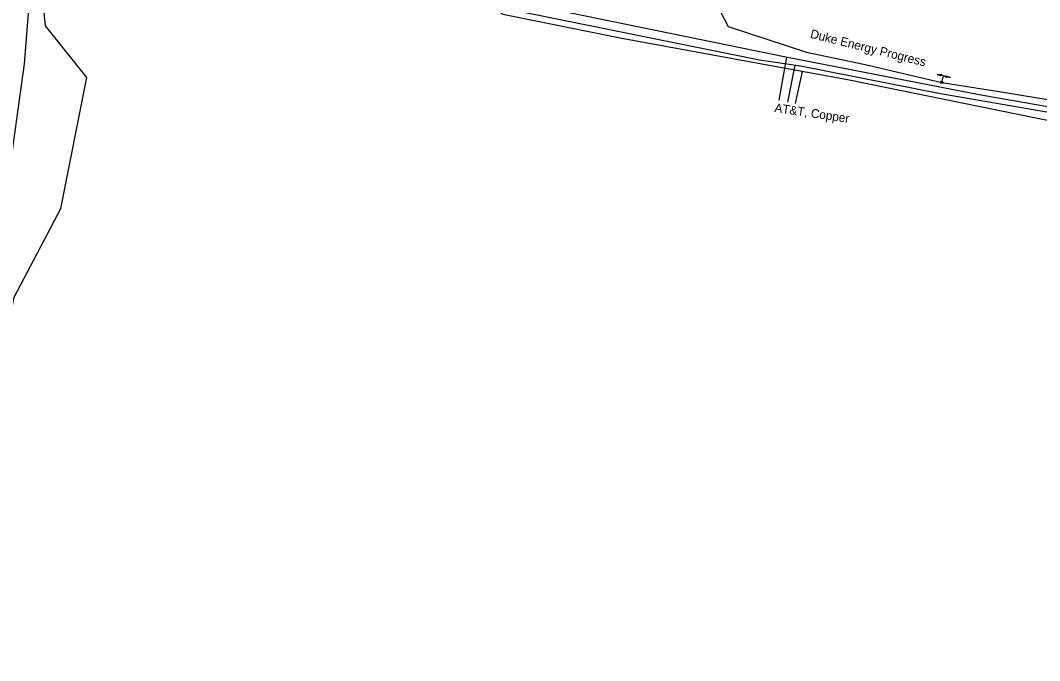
# Model space of a CAD drawing. Extents: x 2070721 to 2083340, y 729290 to 737883.
# Drawn here: x 2082363.4 to 2082825.8, y 735917.7 to 736208.1 of the extents above; entities that cross this region are included whole.
import ezdxf

# ---------------------------------------------------------------- set-up
doc = ezdxf.new("R2010")
doc.units = 0
for name, color, linetype in [('Exist Utilities Power Change of Service SUE CELL', 7, 'Continuous'), ('Exist Utilities Power UG Cable SUE LOS B', 7, 'Continuous'), ('Exist Utilities Power UG Cable SUE LOS C', 7, 'Continuous'), ('Exist Utilities Power UG Cable SUE LOS C Text', 7, 'Continuous'), ('Exist Utilities Telephone UG Cable SUE LOS C', 7, 'Continuous'), ('Exist Utilities Telephone UG Cable SUE LOS C Leader', 7, 'Continuous'), ('Exist Utilities Telephone UG Cable SUE LOS C Text', 7, 'Continuous'), ('Exist Utilities Telephone UG Conduit SUE LOS B', 7, 'Continuous')]:
    doc.layers.add(name, color=color, linetype=linetype)

msp = doc.modelspace()

# ---------------------------------------------------------------- linework, layer by layer
at = {"layer": 'Exist Utilities Power Change of Service SUE CELL'}
for p, q in [((2082785.15, 736182.29), (2082779.35, 736183.65)), ((2082781.39, 736180), (2082782.1, 736183.01)), ((2082782.1, 736183.01), (2082785.15, 736182.29)), ((2082781.39, 736180), (2082781.39, 736180))]:
    msp.add_line(p, q, dxfattribs=at)
for points in [[(2082779.35, 736183.65), (2082781.34, 736183.54), (2082780.86, 736183.3), (2082781.16, 736182.91)], [(2082785.15, 736182.29), (2082783.15, 736182.41), (2082783.64, 736182.65), (2082783.34, 736183.03)]]:
    msp.add_lwpolyline(points, close=True, dxfattribs=at)
msp.add_circle((2082781.39, 736180), 0.517, dxfattribs=at)
at = {"layer": 'Exist Utilities Power UG Cable SUE LOS B'}
msp.add_lwpolyline([(2082781.39, 736180), (2082807.5, 736175.87), (2082843.27, 736169.98), (2082869.14, 736165.45), (2082887.28, 736166.47), (2082906.47, 736166.59), (2082946.98, 736169.49)], dxfattribs=at)
at = {"layer": 'Exist Utilities Power UG Cable SUE LOS C'}
msp.add_lwpolyline([(2082666.83, 736239.42), (2082684.44, 736205.31), (2082720.04, 736193.67), (2082747.93, 736187.86), (2082781.39, 736180)], dxfattribs=at)
at = {"layer": 'Exist Utilities Telephone UG Cable SUE LOS C'}
for points in [[(2082579.78, 736218.88), (2082599.02, 736214.41), (2082710.61, 736191.57), (2082798.37, 736174.45), (2082885.43, 736159.26), (2082946, 736165.14), (2083033.48, 736193.09), (2083077.11, 736211.8), (2083089.57, 736237.13), (2083075.55, 736263.64), (2083044.44, 736310.32), (2083026.72, 736338.29), (2083005.59, 736358.07), (2083003.15, 736369.82)], [(2082575.12, 736215.01), (2082582.19, 736210.9), (2082636.27, 736200.06), (2082738.67, 736181.25), (2082876.05, 736153.29), (2082889.8, 736152.19), (2082917.84, 736153.8), (2082948.81, 736158.4), (2082968.19, 736165.31), (2083046.85, 736194.42), (2083139.27, 736224.96), (2083160, 736232.47), (2083199.9, 736256.41)], [(2082698.76, 736190.27), (2082717.32, 736187.56), (2082780.79, 736175), (2082844.8, 736163.86), (2082884.06, 736155.9), (2082910.3, 736157.05), (2082932.08, 736160.96), (2082946.85, 736162.6), (2082974, 736169.74), (2083009.4, 736182.22), (2083063.26, 736201.82), (2083111.56, 736217.38), (2083126.61, 736221.67), (2083141.61, 736226.58), (2083159.6, 736233.98), (2083198.43, 736258.37)], [(2082576.46, 736214.97), (2082582.9, 736213.6), (2082698.76, 736190.27)]]:
    msp.add_lwpolyline(points, dxfattribs=at)
at = {"layer": 'Exist Utilities Telephone UG Cable SUE LOS C Leader'}
for p, q in [((2082710.95, 736191.5), (2082707.48, 736172)), ((2082714.68, 736187.84), (2082711.35, 736171)), ((2082718.1, 736185.01), (2082714.92, 736170.35))]:
    msp.add_line(p, q, dxfattribs=at)
at = {"layer": 'Exist Utilities Telephone UG Conduit SUE LOS B'}
for points in [[(2082120.86, 735106.65), (2082121.53, 735109.26), (2082126.82, 735163.37), (2082139.88, 735257.28), (2082147.13, 735321.1), (2082170.45, 735428.84), (2082201.87, 735563.79), (2082232.74, 735685.94), (2082254.12, 735726.65), (2082278.69, 735809.1), (2082319.03, 735920.81), (2082334.41, 735993.71), (2082351.13, 736088.05), (2082365.28, 736188.35), (2082370.12, 736249.49)], [(2082311, 735883.41), (2082314.93, 735894.57), (2082321.33, 735919.82), (2082336.09, 735960.51), (2082359.13, 735988.75), (2082348, 736007.91), (2082360.44, 736082.28), (2082381.79, 736122.83), (2082393.52, 736182.23), (2082374.75, 736205.67), (2082370.42, 736249.5)]]:
    msp.add_lwpolyline(points, dxfattribs=at)

# ---------------------------------------------------------------- texts
at = {"layer": 'Exist Utilities Power UG Cable SUE LOS C Text'}
msp.add_text('Duke Energy Progress', height=4, rotation=345.9467, dxfattribs=at).set_placement((2082721.44, 736200.28))
at = {"layer": 'Exist Utilities Telephone UG Cable SUE LOS C Text'}
msp.add_text('AT&T, Copper', height=4, rotation=351.5668, dxfattribs=at).set_placement((2082705.32, 736166.62))

doc.saveas('drawing.dxf')
